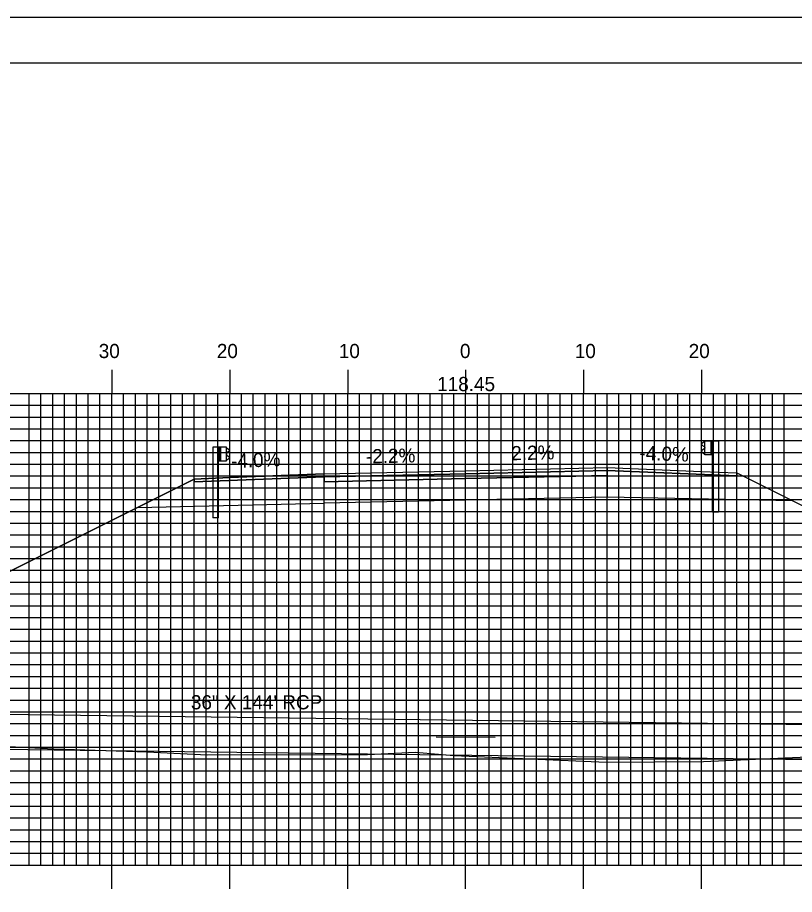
# Model space of a CAD drawing. Extents: x 1786189 to 1786532, y 442591 to 442811.
# Drawn here: x 1786316.6 to 1786382.4, y 442736.2 to 442810.5 of the extents above; entities that cross this region are included whole.
import ezdxf

# ---------------------------------------------------------------- set-up
doc = ezdxf.new("R2010")
doc.units = 0
for name, color, linetype in [('ANNOTATION', 7, 'Continuous'), ('BORDER', 7, 'Continuous'), ('D_Drainage_Culvert', 7, 'Continuous'), ('D_Drainage_Text', 7, 'Continuous'), ('D_Guardrail_Beam_Lt', 7, 'Continuous'), ('D_Guardrail_Beam_Rt', 7, 'Continuous'), ('D_Roadway_Centerline', 7, 'Continuous'), ('D_Roadway_Centerline_Text', 7, 'Continuous'), ('D_Roadway_Edge_Shoulder', 7, 'Continuous'), ('D_Roadway_Edge_TW', 7, 'Continuous'), ('D_Roadway_Pavement', 7, 'Continuous'), ('D_Roadway_SlopeLines', 7, 'Continuous'), ('D_Roadway_SubGrade', 7, 'Continuous'), ('H_V ANNOTATION', 7, 'Continuous'), ('MAJOR', 7, 'Continuous'), ('MINOR', 7, 'Continuous'), ('PLOT BOUNDARY', 7, 'Continuous'), ('S_Roadway_Centerline', 7, 'Continuous')]:
    doc.layers.add(name, color=color, linetype=linetype)

msp = doc.modelspace()

# ---------------------------------------------------------------- linework, layer by layer
at = {"layer": 'BORDER'}
msp.add_lwpolyline([(1786204.965, 442596.665), (1786524.965, 442596.665), (1786524.965, 442806.665), (1786204.965, 442806.665)], close=True, dxfattribs=at)
at = {"layer": 'D_Drainage_Culvert'}
msp.add_line((1786352.071, 442749.551), (1786357.058, 442749.51), dxfattribs=at)
msp.add_lwpolyline([(1786286.414, 442748.831), (1786286.453, 442751.841), (1786430.441, 442749.997), (1786430.402, 442746.987)], close=True, dxfattribs=at)
at = {"layer": 'D_Guardrail_Beam_Lt'}
for p, q in [((1786333.136, 442774.11), (1786333.136, 442768.11)), ((1786333.607, 442774.11), (1786333.136, 442774.11)), ((1786334.294, 442774.11), (1786333.607, 442774.11)), ((1786333.607, 442774.11), (1786333.607, 442772.943)), ((1786333.669, 442774.11), (1786333.669, 442772.943)), ((1786333.773, 442774.11), (1786333.773, 442772.943)), ((1786334.294, 442772.943), (1786334.294, 442774.11)), ((1786334.294, 442774.026), (1786334.368, 442774.012)), ((1786334.384, 442774.005), (1786334.527, 442773.905)), ((1786334.298, 442773.561), (1786334.298, 442773.491)), ((1786334.527, 442773.762), (1786334.332, 442773.626)), ((1786334.332, 442773.427), (1786334.527, 442773.291)), ((1786334.527, 442773.148), (1786334.384, 442773.048)), ((1786333.607, 442772.943), (1786334.294, 442772.943)), ((1786333.627, 442768.11), (1786333.627, 442772.943)), ((1786334.368, 442773.041), (1786334.294, 442773.026)), ((1786333.627, 442768.11), (1786333.136, 442768.11))]:
    msp.add_line(p, q, dxfattribs=at)
for centre, major_axis, start_param, end_param in [((1786334.36, 442773.971), (0.0417, 0), 0.959931, 1.376053), ((1786334.477, 442773.833), (0.0877, 0), 5.323254, 7.243116), ((1786334.377, 442773.561), (-0.0789, 0), 5.323254, 6.283185), ((1786334.377, 442773.491), (-0.0789, 0), 6.283185, 7.243116), ((1786334.477, 442773.219), (0.0877, 0), 5.323254, 7.243116), ((1786334.36, 442773.082), (0.0417, 0), 4.907132, 5.323254)]:
    msp.add_ellipse(centre, major_axis=major_axis, ratio=0.995501, start_param=start_param, end_param=end_param, dxfattribs=at)
at = {"layer": 'D_Guardrail_Beam_Rt'}
for p, q in [((1786374.836, 442774.638), (1786375.523, 442774.638)), ((1786374.836, 442773.471), (1786374.836, 442774.638)), ((1786375.357, 442774.638), (1786375.357, 442773.471)), ((1786375.461, 442774.638), (1786375.461, 442773.471)), ((1786375.523, 442774.638), (1786375.994, 442774.638)), ((1786375.523, 442774.638), (1786375.523, 442773.471)), ((1786375.994, 442774.638), (1786375.994, 442768.638)), ((1786374.746, 442774.533), (1786374.602, 442774.433)), ((1786374.602, 442774.29), (1786374.798, 442774.154)), ((1786374.798, 442773.955), (1786374.602, 442773.819)), ((1786374.836, 442774.554), (1786374.762, 442774.54)), ((1786374.831, 442774.089), (1786374.831, 442774.019)), ((1786374.602, 442773.676), (1786374.746, 442773.576)), ((1786374.762, 442773.569), (1786374.836, 442773.554)), ((1786375.523, 442773.471), (1786374.836, 442773.471)), ((1786375.502, 442768.638), (1786375.502, 442773.471)), ((1786375.502, 442768.638), (1786375.994, 442768.638))]:
    msp.add_line(p, q, dxfattribs=at)
for centre, major_axis, start_param, end_param in [((1786374.653, 442774.361), (-0.0877, 0), 5.323254, 7.243116), ((1786374.77, 442774.499), (-0.0417, 0), 4.907132, 5.323254), ((1786374.752, 442774.089), (0.0789, 0), 0, 0.959931), ((1786374.752, 442774.019), (0.0789, 0), 5.323254, 6.283185), ((1786374.653, 442773.747), (-0.0877, 0), 5.323254, 7.243116), ((1786374.77, 442773.61), (-0.0417, 0), 0.959931, 1.376053)]:
    msp.add_ellipse(centre, major_axis=major_axis, ratio=0.995501, start_param=start_param, end_param=end_param, dxfattribs=at)
at = {"layer": 'D_Roadway_Centerline'}
msp.add_lwpolyline([(1786286.773, 442749.01), (1786326.749, 442768.998), (1786331.565, 442771.406), (1786334.565, 442771.526), (1786342.565, 442771.846), (1786354.565, 442772.11), (1786366.565, 442772.374), (1786374.565, 442772.054), (1786377.565, 442771.934), (1786382.315, 442769.559), (1786427.289, 442747.072)], dxfattribs=at)
at = {"layer": 'D_Roadway_Edge_Shoulder'}
for points in [[(1786366.565, 442772.374), (1786374.565, 442772.054), (1786374.565, 442772.054), (1786377.565, 442771.934), (1786377.565, 442771.684), (1786366.565, 442772.124)], [(1786342.565, 442771.846), (1786334.565, 442771.526), (1786334.565, 442771.526), (1786331.565, 442771.406), (1786331.565, 442771.156), (1786342.565, 442771.596)]]:
    msp.add_lwpolyline(points, close=True, dxfattribs=at)
at = {"layer": 'D_Roadway_Edge_TW'}
msp.add_lwpolyline([(1786342.565, 442771.596), (1786342.565, 442771.846), (1786354.565, 442772.11), (1786366.565, 442772.374), (1786366.565, 442772.124), (1786354.565, 442771.86)], close=True, dxfattribs=at)
at = {"layer": 'D_Roadway_Pavement'}
msp.add_lwpolyline([(1786342.565, 442771.18), (1786342.565, 442771.596), (1786354.565, 442771.86), (1786366.565, 442772.124), (1786366.565, 442771.708), (1786354.565, 442771.444)], close=True, dxfattribs=at)
for points in [[(1786366.565, 442772.124), (1786366.565, 442771.708)], [(1786342.565, 442771.596), (1786342.565, 442771.18)]]:
    msp.add_lwpolyline(points, dxfattribs=at)
at = {"layer": 'D_Roadway_SlopeLines'}
for points in [[(1786377.565, 442771.934), (1786427.289, 442747.072)], [(1786331.565, 442771.406), (1786286.414, 442748.831)]]:
    msp.add_lwpolyline(points, dxfattribs=at)
at = {"layer": 'D_Roadway_SubGrade'}
for points in [[(1786342.565, 442769.346), (1786342.565, 442771.596), (1786342.565, 442771.18), (1786354.565, 442771.444), (1786366.565, 442771.708), (1786366.565, 442772.124), (1786366.565, 442769.874), (1786354.565, 442769.61)], [(1786366.565, 442771.708), (1786366.565, 442772.124), (1786377.565, 442771.684), (1786377.565, 442771.934), (1786382.315, 442769.559), (1786366.565, 442769.874)], [(1786342.565, 442771.18), (1786342.565, 442771.596), (1786331.565, 442771.156), (1786331.565, 442771.406), (1786326.749, 442768.998), (1786342.565, 442769.346)]]:
    msp.add_lwpolyline(points, close=True, dxfattribs=at)
at = {"layer": 'MAJOR'}
for p, q in [((1786324.565, 442780.669), (1786324.565, 442778.665)), ((1786334.565, 442780.669), (1786334.565, 442778.665)), ((1786344.565, 442780.669), (1786344.565, 442778.665)), ((1786354.565, 442780.669), (1786354.565, 442778.665)), ((1786364.565, 442780.669), (1786364.565, 442778.665)), ((1786374.565, 442780.669), (1786374.565, 442778.665)), ((1786214.565, 442778.665), (1786494.565, 442778.665)), ((1786214.565, 442778.665), (1786494.565, 442778.665)), ((1786324.565, 442738.665), (1786324.565, 442778.665)), ((1786334.565, 442738.665), (1786334.565, 442778.665)), ((1786344.565, 442738.665), (1786344.565, 442778.665)), ((1786354.565, 442738.665), (1786354.565, 442778.665)), ((1786364.565, 442738.665), (1786364.565, 442778.665)), ((1786374.565, 442738.665), (1786374.565, 442778.665)), ((1786214.565, 442773.665), (1786494.565, 442773.665)), ((1786214.565, 442768.665), (1786494.565, 442768.665)), ((1786214.565, 442763.665), (1786494.565, 442763.665)), ((1786214.565, 442758.665), (1786494.565, 442758.665)), ((1786214.565, 442753.665), (1786494.565, 442753.665)), ((1786214.565, 442748.665), (1786494.565, 442748.665)), ((1786214.565, 442743.665), (1786494.565, 442743.665)), ((1786214.565, 442738.665), (1786494.565, 442738.665)), ((1786214.565, 442738.665), (1786494.565, 442738.665)), ((1786324.565, 442736.661), (1786324.565, 442738.665)), ((1786334.565, 442736.661), (1786334.565, 442738.665)), ((1786344.565, 442736.661), (1786344.565, 442738.665)), ((1786354.565, 442736.661), (1786354.565, 442738.665)), ((1786364.565, 442736.661), (1786364.565, 442738.665)), ((1786374.565, 442736.661), (1786374.565, 442738.665))]:
    msp.add_line(p, q, dxfattribs=at)
at = {"layer": 'MINOR'}
for p, q in [((1786317.565, 442738.665), (1786317.565, 442778.665)), ((1786318.565, 442738.665), (1786318.565, 442778.665)), ((1786319.565, 442738.665), (1786319.565, 442778.665)), ((1786320.565, 442738.665), (1786320.565, 442778.665)), ((1786321.565, 442738.665), (1786321.565, 442778.665)), ((1786322.565, 442738.665), (1786322.565, 442778.665)), ((1786323.565, 442738.665), (1786323.565, 442778.665)), ((1786325.565, 442738.665), (1786325.565, 442778.665)), ((1786326.565, 442738.665), (1786326.565, 442778.665)), ((1786327.565, 442738.665), (1786327.565, 442778.665)), ((1786328.565, 442738.665), (1786328.565, 442778.665)), ((1786329.565, 442738.665), (1786329.565, 442778.665)), ((1786330.565, 442738.665), (1786330.565, 442778.665)), ((1786331.565, 442738.665), (1786331.565, 442778.665)), ((1786332.565, 442738.665), (1786332.565, 442778.665)), ((1786333.565, 442738.665), (1786333.565, 442778.665)), ((1786335.565, 442738.665), (1786335.565, 442778.665)), ((1786336.565, 442738.665), (1786336.565, 442778.665)), ((1786337.565, 442738.665), (1786337.565, 442778.665)), ((1786338.565, 442738.665), (1786338.565, 442778.665)), ((1786339.565, 442738.665), (1786339.565, 442778.665)), ((1786340.565, 442738.665), (1786340.565, 442778.665)), ((1786341.565, 442738.665), (1786341.565, 442778.665)), ((1786342.565, 442738.665), (1786342.565, 442778.665)), ((1786343.565, 442738.665), (1786343.565, 442778.665)), ((1786345.565, 442738.665), (1786345.565, 442778.665)), ((1786346.565, 442738.665), (1786346.565, 442778.665)), ((1786347.565, 442738.665), (1786347.565, 442778.665)), ((1786348.565, 442738.665), (1786348.565, 442778.665)), ((1786349.565, 442738.665), (1786349.565, 442778.665)), ((1786350.565, 442738.665), (1786350.565, 442778.665)), ((1786351.565, 442738.665), (1786351.565, 442778.665)), ((1786352.565, 442738.665), (1786352.565, 442778.665)), ((1786353.565, 442738.665), (1786353.565, 442778.665)), ((1786355.565, 442738.665), (1786355.565, 442778.665)), ((1786356.565, 442738.665), (1786356.565, 442778.665)), ((1786357.565, 442738.665), (1786357.565, 442778.665)), ((1786358.565, 442738.665), (1786358.565, 442778.665)), ((1786359.565, 442738.665), (1786359.565, 442778.665)), ((1786360.565, 442738.665), (1786360.565, 442778.665)), ((1786361.565, 442738.665), (1786361.565, 442778.665)), ((1786362.565, 442738.665), (1786362.565, 442778.665)), ((1786363.565, 442738.665), (1786363.565, 442778.665)), ((1786365.565, 442738.665), (1786365.565, 442778.665)), ((1786366.565, 442738.665), (1786366.565, 442778.665)), ((1786367.565, 442738.665), (1786367.565, 442778.665)), ((1786368.565, 442738.665), (1786368.565, 442778.665)), ((1786369.565, 442738.665), (1786369.565, 442778.665)), ((1786370.565, 442738.665), (1786370.565, 442778.665)), ((1786371.565, 442738.665), (1786371.565, 442778.665)), ((1786372.565, 442738.665), (1786372.565, 442778.665)), ((1786373.565, 442738.665), (1786373.565, 442778.665)), ((1786375.565, 442738.665), (1786375.565, 442778.665)), ((1786376.565, 442738.665), (1786376.565, 442778.665)), ((1786377.565, 442738.665), (1786377.565, 442778.665)), ((1786378.565, 442738.665), (1786378.565, 442778.665)), ((1786379.565, 442738.665), (1786379.565, 442778.665)), ((1786380.565, 442738.665), (1786380.565, 442778.665)), ((1786381.565, 442738.665), (1786381.565, 442778.665)), ((1786214.565, 442777.665), (1786494.565, 442777.665)), ((1786214.565, 442776.665), (1786494.565, 442776.665)), ((1786214.565, 442775.665), (1786494.565, 442775.665)), ((1786214.565, 442774.665), (1786494.565, 442774.665)), ((1786214.565, 442772.665), (1786494.565, 442772.665)), ((1786214.565, 442771.665), (1786494.565, 442771.665)), ((1786214.565, 442770.665), (1786494.565, 442770.665)), ((1786214.565, 442769.665), (1786494.565, 442769.665)), ((1786214.565, 442767.665), (1786494.565, 442767.665)), ((1786214.565, 442766.665), (1786494.565, 442766.665)), ((1786214.565, 442765.665), (1786494.565, 442765.665)), ((1786214.565, 442764.665), (1786494.565, 442764.665)), ((1786214.565, 442762.665), (1786494.565, 442762.665)), ((1786214.565, 442761.665), (1786494.565, 442761.665)), ((1786214.565, 442760.665), (1786494.565, 442760.665)), ((1786214.565, 442759.665), (1786494.565, 442759.665)), ((1786214.565, 442757.665), (1786494.565, 442757.665)), ((1786214.565, 442756.665), (1786494.565, 442756.665)), ((1786214.565, 442755.665), (1786494.565, 442755.665)), ((1786214.565, 442754.665), (1786494.565, 442754.665)), ((1786214.565, 442752.665), (1786494.565, 442752.665)), ((1786214.565, 442751.665), (1786494.565, 442751.665)), ((1786214.565, 442750.665), (1786494.565, 442750.665)), ((1786214.565, 442749.665), (1786494.565, 442749.665)), ((1786214.565, 442747.665), (1786494.565, 442747.665)), ((1786214.565, 442746.665), (1786494.565, 442746.665)), ((1786214.565, 442745.665), (1786494.565, 442745.665)), ((1786214.565, 442744.665), (1786494.565, 442744.665)), ((1786214.565, 442742.665), (1786494.565, 442742.665)), ((1786214.565, 442741.665), (1786494.565, 442741.665)), ((1786214.565, 442740.665), (1786494.565, 442740.665)), ((1786214.565, 442739.665), (1786494.565, 442739.665))]:
    msp.add_line(p, q, dxfattribs=at)
at = {"layer": 'PLOT BOUNDARY'}
msp.add_lwpolyline([(1786188.778, 442590.547), (1786528.778, 442590.547), (1786528.778, 442810.547), (1786188.778, 442810.547)], close=True, dxfattribs=at)
at = {"layer": 'S_Roadway_Centerline'}
msp.add_lwpolyline([(1786315.332, 442748.759), (1786319.67, 442748.522), (1786327.559, 442748.265), (1786332.667, 442748.024), (1786346.24, 442748.033), (1786350.329, 442748.233), (1786353.553, 442747.967), (1786366.51, 442747.383), (1786374.73, 442747.456), (1786386.058, 442747.945), (1786395.413, 442748.051), (1786407.028, 442747.806), (1786414.013, 442747.513), (1786420.121, 442747.281), (1786428.367, 442747.041), (1786432.417, 442746.933), (1786435.537, 442747.122), (1786456.69, 442747.169), (1786456.783, 442747.164), (1786457.052, 442747.165), (1786476.091, 442747.114), (1786483.098, 442746.93), (1786494.565, 442746.743)], dxfattribs=at)

# ---------------------------------------------------------------- texts
at = {"layer": 'ANNOTATION'}
for s, rotation, p in [('-2.2%', 1.2603, (1786346.124, 442772.725)), ('2.2%', 1.2603, (1786358.445, 442772.996)), ('-4.0%', 357.70939, (1786369.272, 442773.044)), ('-4.0%', 2.29061, (1786334.697, 442772.333))]:
    msp.add_text(s, height=1.2, rotation=rotation, dxfattribs=at).set_placement(p)
at = {"layer": 'D_Drainage_Text'}
msp.add_text('36" X 144\' RCP', height=1.2, dxfattribs=at).set_placement((1786331.276, 442751.874))
at = {"layer": 'D_Roadway_Centerline'}
for s, p in [('C', (1786354.56, 442772.11)), ('L', (1786354.565, 442772.103))]:
    msp.add_text(s, height=0.0146, dxfattribs=at).set_placement(p)
at = {"layer": 'D_Roadway_Centerline_Text'}
msp.add_text('118.45', height=1.2, dxfattribs=at).set_placement((1786352.152, 442778.863))
at = {"layer": 'H_V ANNOTATION'}
for s, p in [('30', (1786323.462, 442781.665)), ('20', (1786333.473, 442781.665)), ('10', (1786343.816, 442781.665)), ('0', (1786354.083, 442781.665)), ('10', (1786363.816, 442781.665)), ('20', (1786373.473, 442781.665))]:
    msp.add_text(s, height=1.2, dxfattribs=at).set_placement(p)

doc.saveas('drawing.dxf')
